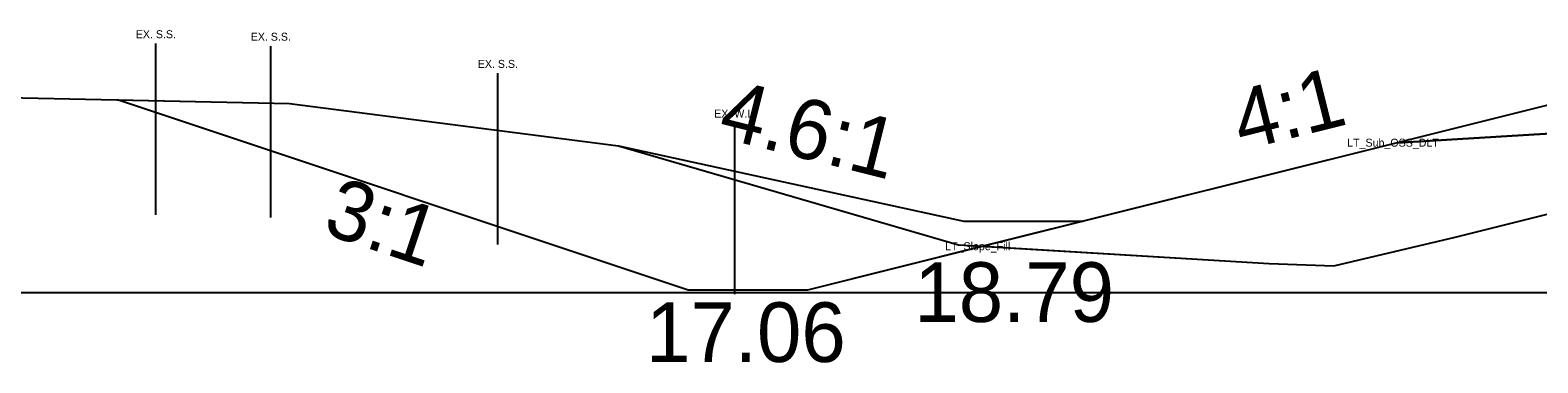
# Model space of a CAD drawing. Extents: x 2177029 to 2201446, y 59897 to 78390.
# Drawn here: x 2200125.09 to 2200162.99, y 66905.54 to 66913.91 of the extents above; entities that cross this region are included whole.
import ezdxf

# ---------------------------------------------------------------- set-up
doc = ezdxf.new("R2010")
doc.units = 0
for name, color, linetype in [('Exist Cross Section Cell', 7, 'Continuous'), ('Exist PHM Roadway Shape', 7, 'Continuous'), ('Exist XS Ground Line', 7, 'Continuous'), ('Old_Level_1', 7, 'Continuous'), ('Prop CMT Guardrail Widen Shoulder', 7, 'Continuous'), ('Prop CMT Pvmt Course 3', 7, 'Continuous'), ('Prop CMT Pvmt Surface Shoulder', 7, 'Continuous'), ('Prop CMT Top Wall Envelope', 7, 'Continuous'), ('Prop Hatching', 7, 'Continuous'), ('Prop XS Earthwork Shape', 7, 'Continuous'), ('Prop XS Side Slope Text', 7, 'Continuous')]:
    doc.layers.add(name, color=color, linetype=linetype)

msp = doc.modelspace()

# ---------------------------------------------------------------- linework, layer by layer
at = {"layer": 'Exist Cross Section Cell'}
msp.add_line((2200042.732, 66907.31), (2200242.732, 66907.31), dxfattribs=at)
at = {"layer": 'Exist XS Ground Line'}
msp.add_lwpolyline([(2200123.705, 66912.231), (2200131.606, 66912.059), (2200139.88, 66911), (2200148.428, 66908.509), (2200156.242, 66908.04), (2200157.864, 66907.975), (2200160.916, 66908.697), (2200175.302, 66912.295)], dxfattribs=at)
at = {"layer": 'Old_Level_1'}
for p, q in [((2200139.88, 66911), (2200148.566, 66909.103)), ((2200148.566, 66909.103), (2200151.566, 66909.103))]:
    msp.add_line(p, q, dxfattribs=at)
at = {"layer": 'Prop CMT Pvmt Course 3'}
msp.add_lwpolyline([(2200165.658, 66911.448), (2200159.459, 66911.076)], dxfattribs=at)
at = {"layer": 'Prop CMT Pvmt Surface Shoulder'}
msp.add_line((2200142.793, 66911.573), (2200142.793, 66907.265), dxfattribs=at)
at = {"layer": 'Prop Hatching'}
for p, q in [((2200141.634, 66907.37), (2200127.287, 66912.153)), ((2200144.634, 66907.37), (2200141.634, 66907.37))]:
    msp.add_line(p, q, dxfattribs=at)
msp.add_lwpolyline([(2200166.721, 66912.512), (2200164.722, 66912.392), (2200144.634, 66907.37)], dxfattribs=at)
at = {"layer": 'Prop XS Earthwork Shape'}
for p, q in [((2200128.243, 66913.567), (2200128.243, 66909.259)), ((2200131.133, 66913.505), (2200131.133, 66909.197)), ((2200136.84, 66912.822), (2200136.84, 66908.514))]:
    msp.add_line(p, q, dxfattribs=at)
at = {"layer": 'Prop XS Side Slope Text'}
for points in [[(2200127.287, 66912.153), (2200131.606, 66912.059), (2200139.88, 66911), (2200148.428, 66908.509), (2200149.04, 66908.472), (2200144.634, 66907.37), (2200141.634, 66907.37)], [(2200156.242, 66908.04), (2200157.864, 66907.975), (2200160.916, 66908.697), (2200173.889, 66911.942), (2200165.658, 66911.448), (2200159.458, 66911.076), (2200149.04, 66908.472)]]:
    msp.add_lwpolyline(points, close=True, dxfattribs=at)
msp.add_lwpolyline([(2200164.722, 66912.392), (2200159.458, 66911.076), (2200165.658, 66911.448)], dxfattribs=at)

# ---------------------------------------------------------------- texts
at = {"layer": 'Exist PHM Roadway Shape'}
for s, p in [('LT_Sub_OSS_DLT', (2200158.199, 66910.976)), ('LT_Slope_Fill', (2200148.093, 66908.372))]:
    msp.add_text(s, height=0.2, dxfattribs=at).set_placement(p)
at = {"layer": 'Old_Level_1'}
msp.add_text('4.6:1', height=1.5, rotation=345.9635, dxfattribs=at).set_placement((2200142.344, 66911.227))
msp.add_text('18.79', height=1.5, dxfattribs=at).set_placement((2200147.319, 66906.568))
at = {"layer": 'Prop CMT Guardrail Widen Shoulder'}
msp.add_text('4:1', height=1.5, rotation=14.0355, dxfattribs=at).set_placement((2200155.546, 66910.872))
at = {"layer": 'Prop CMT Pvmt Surface Shoulder'}
msp.add_text('EX. W.L.', height=0.2, dxfattribs=at).set_placement((2200142.287, 66911.708))
at = {"layer": 'Prop CMT Top Wall Envelope'}
msp.add_text('3:1', height=1.5, rotation=341.5651, dxfattribs=at).set_placement((2200132.401, 66908.813))
msp.add_text('17.06', height=1.5, dxfattribs=at).set_placement((2200140.574, 66905.561))
at = {"layer": 'Prop XS Earthwork Shape'}
for p in [(2200127.745, 66913.703), (2200130.635, 66913.64), (2200136.343, 66912.957)]:
    msp.add_text('EX. S.S.', height=0.2, dxfattribs=at).set_placement(p)

doc.saveas('drawing.dxf')
